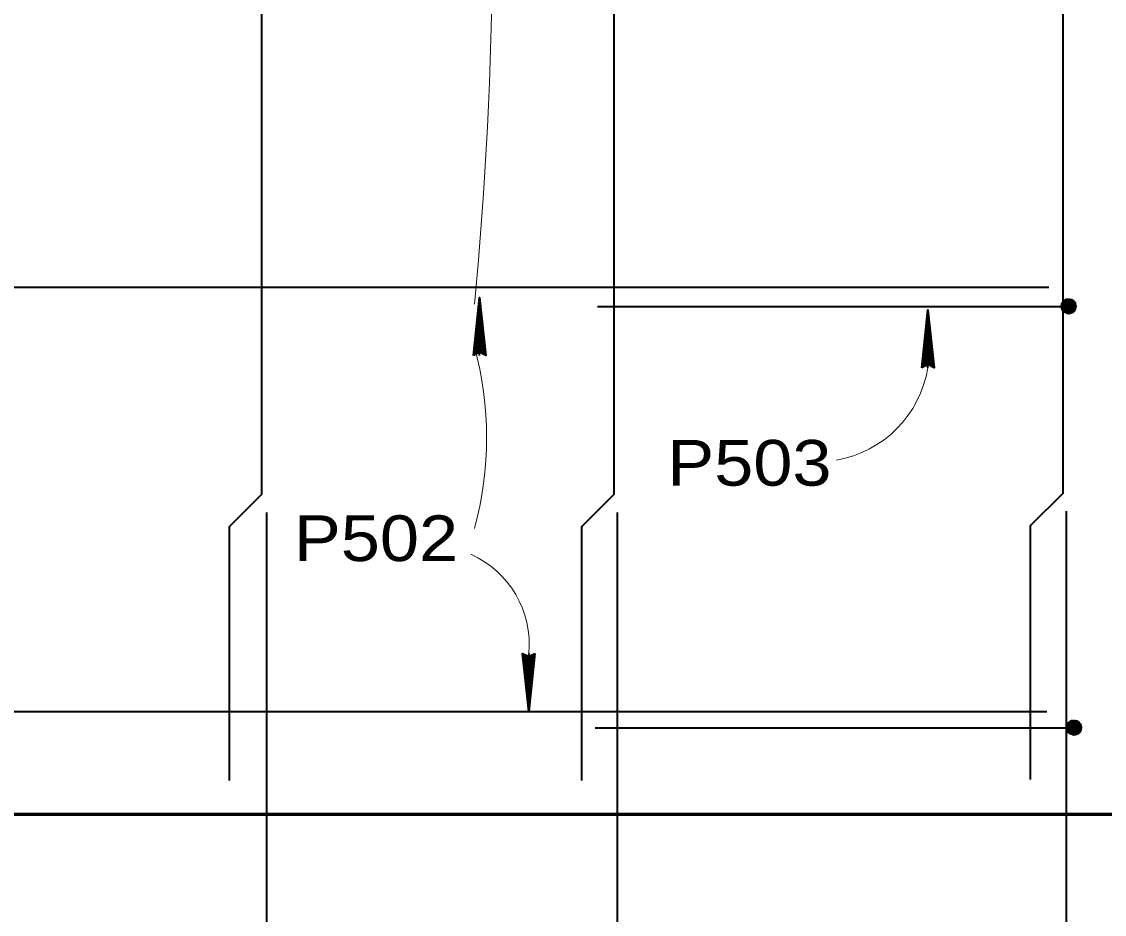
# Model space of a CAD drawing. Extents: x 6.34 to 9.53, y -1.46 to 0.53.
# Drawn here: x 7.1006 to 7.298, y -0.7412 to -0.5784 of the extents above; entities that cross this region are included whole.
import ezdxf

# ---------------------------------------------------------------- set-up
doc = ezdxf.new("R2010")
doc.units = 0
doc.header["$LTSCALE"] = 0.0033
doc.layers.add('1', color=7, linetype='Continuous', lineweight=40)

msp = doc.modelspace()

# ---------------------------------------------------------------- linework, layer by layer
at = {"layer": '1', "lineweight": 35}
for p, q in [((7.184083, -0.63925), (7.184083, -0.628667)), ((7.183083, -0.639), (7.184, -0.631167)), ((7.183083, -0.639), (7.184, -0.631167)), ((7.183167, -0.639), (7.184, -0.631167)), ((7.18325, -0.639), (7.184083, -0.631167)), ((7.18325, -0.639), (7.18425, -0.631167)), ((7.184917, -0.639), (7.184083, -0.631667)), ((7.185, -0.639), (7.18425, -0.631667)), ((7.185167, -0.639), (7.184333, -0.631667)), ((7.265833, -0.6415), (7.265833, -0.630917)), ((7.18475, -0.639083), (7.184, -0.63175)), ((7.264833, -0.64125), (7.26575, -0.633417)), ((7.264833, -0.64125), (7.26575, -0.633417)), ((7.264917, -0.64125), (7.26575, -0.633417)), ((7.265, -0.64125), (7.265833, -0.633417)), ((7.265, -0.64125), (7.266, -0.633417)), ((7.2665, -0.641333), (7.26575, -0.634)), ((7.266667, -0.64125), (7.265833, -0.633917)), ((7.26675, -0.64125), (7.266, -0.633917)), ((7.266917, -0.64125), (7.266083, -0.633917)), ((7.192, -0.693833), (7.192833, -0.701167)), ((7.192167, -0.693833), (7.192917, -0.701167)), ((7.19225, -0.693833), (7.193083, -0.701167)), ((7.192417, -0.69375), (7.193167, -0.701083)), ((7.193917, -0.693833), (7.192917, -0.701667)), ((7.193083, -0.693583), (7.193083, -0.704167)), ((7.193917, -0.693833), (7.193083, -0.701667)), ((7.194083, -0.693833), (7.193167, -0.701667)), ((7.194083, -0.693833), (7.193167, -0.701667)), ((7.194, -0.693833), (7.193167, -0.701667))]:
    msp.add_line(p, q, dxfattribs=at)
at = {"layer": '1'}
for p, q in [((7.290583, -0.6295), (7.2905, -0.631)), ((7.290667, -0.6295), (7.290583, -0.631)), ((7.290583, -0.6295), (7.292583, -0.629833)), ((7.290583, -0.629583), (7.292583, -0.629917)), ((7.290583, -0.629667), (7.292583, -0.630083)), ((7.290667, -0.629333), (7.292583, -0.629667)), ((7.29075, -0.6295), (7.290667, -0.631)), ((7.290833, -0.6295), (7.29075, -0.631)), ((7.290917, -0.6295), (7.290833, -0.631)), ((7.291083, -0.6295), (7.291, -0.631)), ((7.291167, -0.6295), (7.291083, -0.631)), ((7.29125, -0.6295), (7.291167, -0.631)), ((7.291333, -0.6295), (7.29125, -0.631)), ((7.291417, -0.6295), (7.291333, -0.631)), ((7.2915, -0.6295), (7.291417, -0.631)), ((7.291583, -0.6295), (7.2915, -0.631)), ((7.29175, -0.629583), (7.291583, -0.631083)), ((7.291917, -0.629583), (7.29175, -0.631083)), ((7.292, -0.629583), (7.291917, -0.631083)), ((7.292, -0.629583), (7.291917, -0.631083)), ((7.292083, -0.629583), (7.292, -0.631083)), ((7.292167, -0.629583), (7.292083, -0.631083)), ((7.29225, -0.629583), (7.292167, -0.631083)), ((7.292333, -0.629583), (7.29225, -0.631083)), ((7.292417, -0.629583), (7.292333, -0.631083)), ((7.2925, -0.629583), (7.292417, -0.631083)), ((7.292667, -0.629583), (7.292583, -0.631083)), ((7.205583, -0.630333), (7.290083, -0.630333)), ((7.290333, -0.630917), (7.292333, -0.63125)), ((7.290417, -0.630417), (7.292417, -0.630833)), ((7.290417, -0.630667), (7.292417, -0.631)), ((7.290417, -0.63075), (7.292333, -0.631083)), ((7.290417, -0.630833), (7.292333, -0.631167)), ((7.2905, -0.63), (7.2925, -0.630333)), ((7.2905, -0.630083), (7.2925, -0.6305)), ((7.2905, -0.630167), (7.292417, -0.630583)), ((7.2905, -0.63025), (7.292417, -0.630667)), ((7.290583, -0.62975), (7.292583, -0.630167)), ((7.290583, -0.629917), (7.2925, -0.63025)), ((7.14525, -0.667917), (7.14525, -0.780417)), ((7.209167, -0.667917), (7.209167, -0.780333)), ((7.291083, -0.667667), (7.291083, -0.78)), ((7.291583, -0.706333), (7.2915, -0.707833)), ((7.291667, -0.706333), (7.291583, -0.707833)), ((7.291583, -0.706333), (7.293583, -0.706667)), ((7.291583, -0.706417), (7.293583, -0.70675)), ((7.291583, -0.7065), (7.293583, -0.706917)), ((7.291583, -0.706583), (7.293583, -0.707)), ((7.291667, -0.706167), (7.293583, -0.7065)), ((7.29175, -0.706333), (7.291667, -0.707833)), ((7.291833, -0.706333), (7.29175, -0.707833)), ((7.291917, -0.706333), (7.291833, -0.707833)), ((7.292083, -0.706333), (7.292, -0.707833)), ((7.292167, -0.706333), (7.292083, -0.707833)), ((7.29225, -0.706333), (7.292167, -0.707833)), ((7.292333, -0.706333), (7.29225, -0.707833)), ((7.292417, -0.706333), (7.292333, -0.707833)), ((7.2925, -0.706333), (7.292417, -0.707833)), ((7.292583, -0.706333), (7.2925, -0.707833)), ((7.29275, -0.706417), (7.292583, -0.707917)), ((7.292917, -0.706417), (7.29275, -0.707917)), ((7.293, -0.706417), (7.292917, -0.707917)), ((7.293, -0.706417), (7.292917, -0.707917)), ((7.293083, -0.706417), (7.293, -0.707917)), ((7.293167, -0.706417), (7.293083, -0.707917)), ((7.29325, -0.706417), (7.293167, -0.707917)), ((7.293333, -0.706417), (7.29325, -0.707917)), ((7.293417, -0.706417), (7.293333, -0.707917)), ((7.2935, -0.706417), (7.293417, -0.707917)), ((7.293667, -0.706417), (7.293583, -0.707917)), ((7.205167, -0.707167), (7.291083, -0.707167)), ((7.291333, -0.70775), (7.293333, -0.708083)), ((7.291417, -0.70725), (7.293417, -0.707667)), ((7.291417, -0.7075), (7.293417, -0.707833)), ((7.291417, -0.707583), (7.293333, -0.707917)), ((7.291417, -0.707667), (7.293333, -0.708)), ((7.2915, -0.706833), (7.2935, -0.707167)), ((7.2915, -0.706917), (7.2935, -0.707333)), ((7.2915, -0.707), (7.293417, -0.707417)), ((7.2915, -0.707083), (7.293417, -0.7075)), ((7.291583, -0.70675), (7.2935, -0.707083))]:
    msp.add_line(p, q, dxfattribs=at)
for points in [[(7.138417, -0.407), (7.138417, -0.450333), (7.144333, -0.45625), (7.144333, -0.664583), (7.138417, -0.6705), (7.138417, -0.71675)], [(7.202667, -0.407), (7.202667, -0.450333), (7.208583, -0.45625), (7.208583, -0.664583), (7.202667, -0.6705), (7.202667, -0.71675)], [(7.2845, -0.406833), (7.2845, -0.450167), (7.290417, -0.456083), (7.290417, -0.664417), (7.2845, -0.670333), (7.2845, -0.716583)], [(6.737, -0.626833), (6.962167, -0.626833), (7.287917, -0.626833)], [(7.290167, -0.630333), (7.29275, -0.63), (7.290417, -0.6295), (7.29275, -0.630583), (7.290333, -0.631), (7.292333, -0.631333), (7.292333, -0.62925), (7.291417, -0.631583), (7.291667, -0.629), (7.290667, -0.631333), (7.291, -0.629), (7.291833, -0.631583), (7.29025, -0.629833), (7.292667, -0.629667), (7.291, -0.6315), (7.292083, -0.629083), (7.290417, -0.6295), (7.290333, -0.631), (7.291417, -0.631583), (7.292333, -0.631333), (7.29275, -0.630583), (7.292667, -0.629667), (7.292083, -0.629083), (7.291417, -0.630167), (7.292583, -0.631083), (7.290667, -0.631333), (7.291417, -0.630167), (7.290333, -0.629667), (7.291333, -0.629), (7.291417, -0.630083), (7.29225, -0.631333), (7.29025, -0.630083), (7.291583, -0.62975), (7.292333, -0.62925)], [(6.736583, -0.704167), (6.962167, -0.704167), (7.2875, -0.704167)], [(7.291167, -0.707167), (7.29375, -0.706833), (7.291417, -0.706333), (7.29375, -0.707417), (7.291333, -0.707833), (7.293333, -0.708167), (7.293333, -0.706083), (7.292417, -0.708417), (7.292667, -0.705833), (7.291667, -0.708167), (7.292, -0.705833), (7.292833, -0.708417), (7.29125, -0.706667), (7.293667, -0.7065), (7.292, -0.708333), (7.293083, -0.705917), (7.291417, -0.706333), (7.291333, -0.707833), (7.292417, -0.708417), (7.293333, -0.708167), (7.29375, -0.707417), (7.293667, -0.7065), (7.293083, -0.705917), (7.292417, -0.707), (7.293583, -0.707917), (7.291667, -0.708167), (7.292417, -0.707), (7.291333, -0.7065), (7.292333, -0.705833), (7.292417, -0.706917), (7.29325, -0.708167), (7.29125, -0.706917), (7.292583, -0.706583), (7.293333, -0.706083)]]:
    msp.add_lwpolyline(points, dxfattribs=at)
at = {"layer": '1', "lineweight": 35}
for points in [[(7.183, -0.63925), (7.184083, -0.628667), (7.18525, -0.63925), (7.184083, -0.638667)], [(7.184, -0.6385), (7.183917, -0.633833), (7.184, -0.633833), (7.184, -0.63475), (7.183917, -0.6385), (7.183833, -0.6355), (7.18375, -0.638667), (7.183667, -0.636417), (7.183583, -0.638667), (7.183833, -0.635167), (7.184, -0.6305), (7.18425, -0.631417), (7.18425, -0.630167), (7.18425, -0.6385), (7.184417, -0.636083), (7.184417, -0.638667), (7.184, -0.633333), (7.184667, -0.638667)], [(7.26475, -0.6415), (7.265833, -0.630917), (7.267, -0.6415), (7.265833, -0.640917)], [(7.26575, -0.64075), (7.265667, -0.636083), (7.26575, -0.636083), (7.26575, -0.637), (7.265667, -0.64075), (7.265583, -0.63775), (7.2655, -0.640917), (7.265417, -0.638667), (7.265333, -0.640917), (7.265583, -0.637417), (7.26575, -0.63275), (7.266, -0.633667), (7.266, -0.632417), (7.266, -0.64075), (7.266167, -0.638333), (7.266167, -0.640917), (7.26575, -0.635583), (7.266417, -0.640917)], [(7.194167, -0.693583), (7.193083, -0.704167), (7.191917, -0.693583), (7.193083, -0.694167)], [(7.193167, -0.694333), (7.19325, -0.699), (7.193167, -0.699), (7.193167, -0.698083), (7.19325, -0.694333), (7.193333, -0.697333), (7.193417, -0.694167), (7.1935, -0.696417), (7.193583, -0.694167), (7.193333, -0.697667), (7.193167, -0.702333), (7.192917, -0.701417), (7.192917, -0.702667), (7.192917, -0.694333), (7.19275, -0.69675), (7.19275, -0.694167), (7.193167, -0.6995), (7.1925, -0.694167)]]:
    msp.add_lwpolyline(points, close=True, dxfattribs=at)
for points in [[(7.184, -0.6385), (7.18325, -0.638917), (7.1835, -0.638667), (7.183833, -0.6385), (7.18375, -0.63825), (7.183417, -0.638417), (7.184167, -0.638583), (7.184667, -0.63875), (7.185083, -0.639)], [(7.26575, -0.64075), (7.265, -0.641167), (7.26525, -0.640917), (7.265583, -0.64075), (7.2655, -0.6405), (7.265167, -0.640667), (7.265917, -0.640833), (7.266417, -0.641), (7.266833, -0.64125)], [(7.193167, -0.694333), (7.193917, -0.693917), (7.193667, -0.694167), (7.193333, -0.694333), (7.193417, -0.694583), (7.19375, -0.694417), (7.193, -0.69425), (7.1925, -0.694083), (7.192083, -0.693833)]]:
    msp.add_lwpolyline(points, dxfattribs=at)
at = {"layer": '1', "lineweight": 60}
msp.add_lwpolyline([(6.718917, -0.722917), (6.962083, -0.722917), (7.30225, -0.722917)], dxfattribs=at)
at = {"layer": '1'}
for centre in [(7.2915, -0.630283), (7.2925, -0.707117)]:
    msp.add_circle(centre, 0.00132, dxfattribs=at)
at = {"layer": '1', "lineweight": 13}
for centre, radius, start, end in [((6.434053, -0.558971), 0.752466, 354.58985, 4.45032), ((7.121955, -0.65425), 0.063418, 344.84139, 15.15861), ((7.245697, -0.638231), 0.0204, 279.79151, 350.77859), ((7.17517, -0.691928), 0.017989, 354.72179, 65.95511)]:
    msp.add_arc(centre, radius, start, end, dxfattribs=at)

# ---------------------------------------------------------------- texts
at = {"layer": '1', "width": 1.15}
for s, p in [('P503', (7.218333, -0.663)), ('P502', (7.15025, -0.67675))]:
    msp.add_text(s, height=0.008334, dxfattribs=at).set_placement(p)

doc.saveas('drawing.dxf')
